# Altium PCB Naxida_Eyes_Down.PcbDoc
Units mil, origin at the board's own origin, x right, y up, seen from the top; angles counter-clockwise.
Board outline 2236.22 x 1401.57 mil, 2 copper layers (Top Layer, Bottom Layer); 34 components, 21 nets, 111 pads, 121 vias.
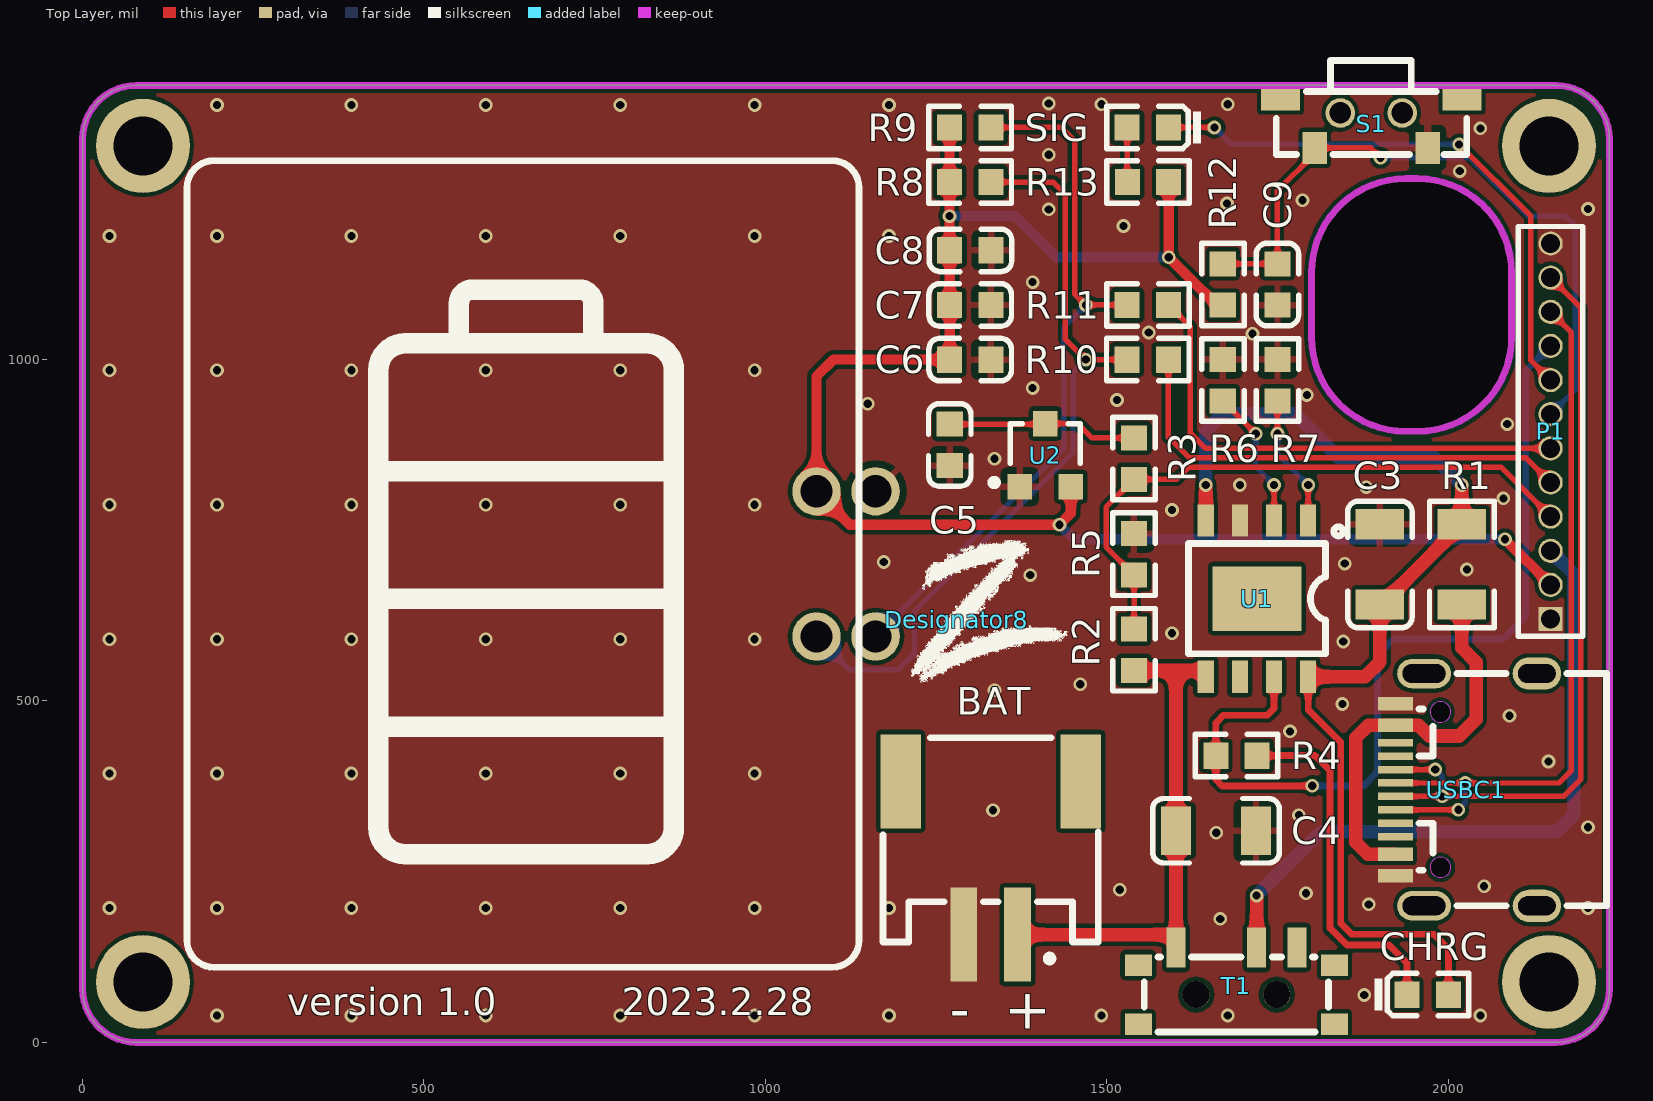
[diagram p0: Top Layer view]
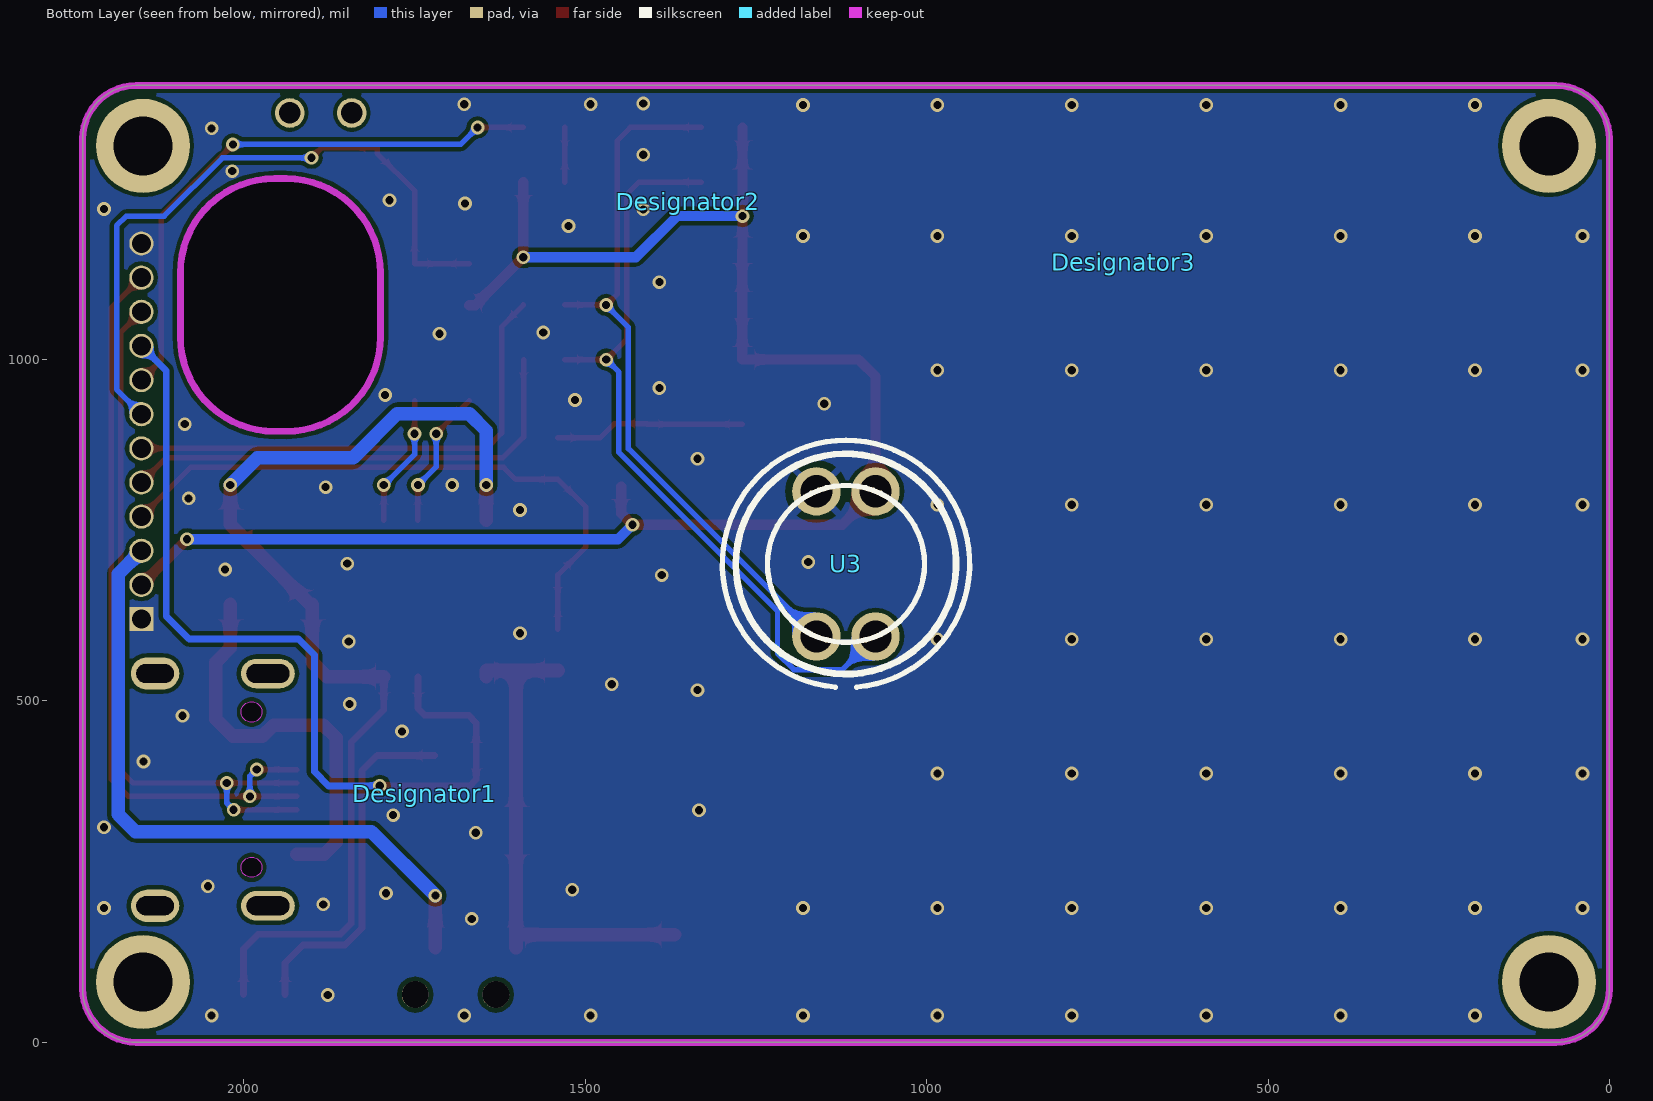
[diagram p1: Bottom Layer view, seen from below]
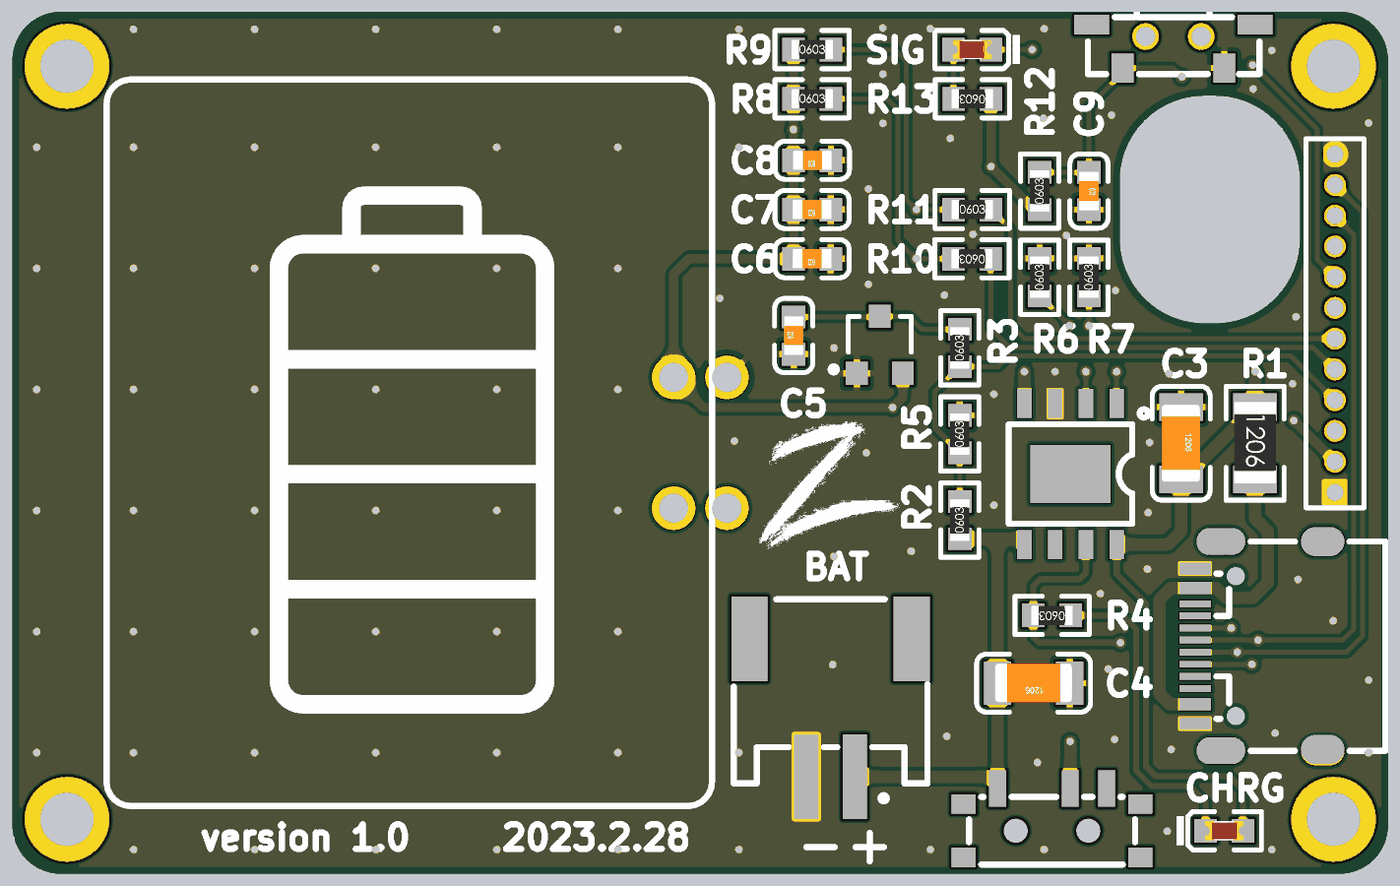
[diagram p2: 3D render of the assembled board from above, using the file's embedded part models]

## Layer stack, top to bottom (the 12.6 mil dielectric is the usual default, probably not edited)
Top Solder: solder mask 0.4, Solder Resist, Dk 3.5
Top Layer: signal copper 1.4
Dielectric 1: dielectric 12.6, FR-4, Dk 4.8
Bottom Layer: signal copper 1.4
Bottom Solder: solder mask 0.4, Solder Resist, Dk 3.5

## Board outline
78.74,0 cw(c78.74,78.74) 0,78.74 0,1322.83 cw(c78.74,1322.83) 78.74,1401.57 2157.48,1401.57 cw(c2157.48,1322.83) 2236.22,1322.83 2236.22,78.74 cw(c2157.48,78.74) 2157.48,0
cut-out: 1800,1032.58 ccw(c1937.58,1032.58) 1937.58,895 1955.2,895 ccw(c1955.2,1032.8) 2093,1032.8 2093,1127.2 ccw(c1955.2,1127.2) 1955.2,1265 1937.8,1265 ccw(c1937.8,1127.2) 1800,1127.2

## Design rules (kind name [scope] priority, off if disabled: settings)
Clearance [All] p1: gap=6 ignorepadtopadclearanceinfootprint=TRUE except(5: Arc-Via Track-Via SMDPad-Via THPad-Via Via-Via)
PolygonConnect PolygonConnect_2 [HasPad('P1-1','P1-12','U1-3','BAT-2','USBC1-A1','USBC1-A12')] p1: connectstyle=Direct reliefconductorwidth=10 reliefentries=4 polygonreliefangle="90 Angle" airgapwidth=10
PolygonConnect PolygonConnect_1 [IsVia] p2: connectstyle=Direct reliefconductorwidth=10 reliefentries=4 polygonreliefangle="90 Angle" airgapwidth=10
PolygonConnect [All] p3: connectstyle=Relief reliefconductorwidth=10 reliefentries=4 polygonreliefangle="90 Angle" airgapwidth=10
RoutingVias [All] p1: holewidth=12 width=20 viastyle="Through Hole" minholewidth=12 minwidth=20 maxholewidth=28 maxwidth=50
SolderMaskExpansion [All] p1: expansion=4 istentingtop=FALSE
Width [All] p1: maxlimit=30 minlimit=6 preferedwidth=8
30 further rules are at their usual default settings.

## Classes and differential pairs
component class Naxida_Eyes_Down: BAT C3 C4 C5 C6 C7 C8 C9 CHRG P1 R1 R2 R3 R4 R5 R6 R7 R8 R9 R10 R11 R12 R13 S1 SIG T1 U1 U2 U3 USBC1

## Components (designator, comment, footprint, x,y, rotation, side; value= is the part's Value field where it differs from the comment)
BAT "Header 2*1" COM_T_2.0_2P 1330,270 r180 top (schematic designator BAT1)
C3 "10uF" LC-1206_C 1900,700 r270 top
C4 "10uF" LC-1206_C 1660,310 r180 top
C5 "0.1uF" LC-0603_C 1270,875 r90 top
C6 "4.7uF" LC-0603_C 1300,1000 r180 top
C7 "0.1uF" LC-0603_C 1300,1080 r180 top
C8 "10nF" LC-0603_C 1300.32,1160 r180 top
C9 "Cap" LC-0603_C 1750,1110 r270 top value=0.1uF
CHRG "LED0" LC-0603_LED_S1 1970,70 r0 top
Designator1 "Comment" Z_NAHIDA_1 1735,365 r180 bottom locked
Designator2 "Comment" Z_NAHIDA_3 1349.49,1232.17 r180 bottom locked
Designator3 "Comment" Z_NAHIDA_4 711.43,1143.16 r180 bottom locked
Designator8 "Comment" Z_LOGO_MINI 1280,620 r0 top
P1 "Header 12*1" HDR12X1_A-1.27mm 2150,620 r90 top
R1 "0.4R" LC-1206_R 2020,700 r270 top
R2 "4.7K" LC-0603_R 1540,575 r90 top
R3 "1K" LC-0603_R 1540,855 r90 top
R4 "1.5K" LC-0603_R 1690,420 r180 top
R5 "4.7K" LC-0603_R 1540,715 r90 top
R6 "1.2K" LC-0603_R 1670,970 r90 top
R7 "4.7K" LC-0603_R 1750,970 r90 top
R8 "4.7K" LC-0603_R 1300,1260 r0 top
R9 "4.7K" LC-0603_R 1300,1340 r0 top
R10 "120R" LC-0603_R 1560,1000 r180 top
R11 "120R" LC-0603_R 1560.31,1080 r0 top
R12 "Res1" LC-0603_R 1670,1110 r90 top value=4.7K
R13 "Res1" LC-0603_R 1560.47,1260 r180 top value=4.7K
S1 "SW-PB" KEY_3*6*3.5 1884.11,1302.95 r180 top
SIG "LED0" LC-0603_LED_S1 1560.16,1340 r180 top
T1 "Header 3*1" KEY_3*7 1690,70 r180 top
U1 "TP4056" ESOP_4056 1720,650 r180 top
U2 "BAT54S" SOT-23 1410,860 r0 top
U3 "MLX90640" MLX90640 1118.11,700.79 r0 bottom locked
USBC1 "TYPE-C" TYPE-C-16P 2026.3,370.1 r90 top locked

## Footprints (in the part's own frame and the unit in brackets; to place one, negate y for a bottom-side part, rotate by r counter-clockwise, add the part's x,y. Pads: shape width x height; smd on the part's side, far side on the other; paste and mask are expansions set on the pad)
COM_T_2.0_2P [mm]
  rect 1x3.5 smd: 1(-1,2.85) 2(1,2.85)
  rect 1.5x3.5 smd: 3(3.35,-2.85) 4(-3.35,-2.85)
  silkscreen extent -4,-4.48 4,3.87
ESOP_4056 [mm]
  rect 0.6x1.2 smd mask+0.051: 1(-1.905,-2.908) 2(-0.635,-2.908) 3(0.635,-2.908) 4(1.905,-2.908) 5(1.905,2.908) 6(0.635,2.908) 7(-0.635,2.908) 8(-1.905,2.908)
  rect 3.3x2.4 smd mask+0.051: 9(0,0)
  silkscreen extent -3.2,-2.67 2.55,2.05
HDR12X1_A-1.27mm [mm] "Connector; Header; 12 Position"
  rect 0.9x0.9 hole 0.7: 1(0,0)
  round 0.9 hole 0.7: 2(1.27,0) 3(2.54,0) 4(3.81,0) 5(5.08,0) 6(6.35,0) 7(7.62,0) 8(8.89,0) 9(10.16,0) 10(11.43,0) 11(12.7,0) 12(13.97,0)
  silkscreen extent -0.64,-1.2 14.6,1.2
KEY_3*6*3.5 [mm]
  rect 0.9x1.2 smd: 1(-2.182,-0.179) 2(2.018,-0.179)
  rect 1.45x0.8 smd: ""(-3.457,-1.971) ""(3.293,-1.971)
  round 1.1 hole 0.8 unplated: ""(-1.232,-1.479) ""(1.068,-1.479)
  silkscreen extent -3.64,-3.43 3.45,0.07
KEY_3*7 [mm]
  rect 0.7x1.5 smd: 1(2.25,-1.75) 2(-0.75,-1.75) 3(-2.25,-1.75)
  rect 1x0.8 smd: 4(-3.65,1.1) 5(-3.65,-1.1) 6(3.65,-1.1) 7(3.65,1.1)
  round 1 hole 1 unplated: ""(-1.5,0) ""(1.5,0)
  silkscreen extent -3.43,-1.4 3.43,1.4
LC-0603_C [mm]
  rect 0.93x0.98 smd: 1(-0.77,0) 2(0.77,0)
  silkscreen extent -1.53,-0.79 1.54,0.79, body extent -0.8,-0.4 0.8,0.4, height 0.3
LC-0603_LED_S1 [mm]
  rect 0.93x0.98 smd: 1(0.77,0) 2(-0.77,0)
  silkscreen extent -1.98,-0.79 1.54,0.79, body extent -0.8,-0.4 0.8,0.4, height 0.6
LC-0603_R [mm]
  rect 0.93x0.98 smd: 1(-0.77,0) 2(0.77,0)
  silkscreen extent -1.53,-0.79 1.54,0.79, body extent -0.85,-0.4 0.85,0.4, height 0.56
LC-1206_C [mm]
  rect 1.13x1.8 smd: 1(-1.49,0) 2(1.49,0)
  silkscreen extent -2.36,-1.2 2.35,1.2, body extent -1.6,-0.81 1.6,0.79, height 1
LC-1206_R [mm]
  rect 1.13x1.8 smd: 1(-1.49,0) 2(1.49,0)
  silkscreen extent -2.36,-1.2 2.35,1.2, body extent -1.7,-0.86 1.65,0.87, height 0.85
MLX90640 [mm]
  round 1.8 hole 1.2 copper offset 0.001,0 mask+0.05: 1(-1.1,2.701) 2(-1.1,-2.699) 3(1.101,-2.699) 4(1.101,2.701)
  silkscreen extent -4.6,-4.6 4.6,4.58
SOT-23 [mm]
  rect 0.9x0.95 smd: 1(-0.95,-1.175) 2(0.95,-1.175) 3(0,1.175)
  silkscreen extent -2.03,-1.14 1.3,1.18, body extent -1.7,-0.8 1.7,0.8, height 1.5
TYPE-C-16P [mil]
  oval 47.2x70.9 hole 27.6 slot 55.1 at 90 deg mask+2: 0(-170.1,-103.7) 0(170.1,-103.7)
  oval 43.3x78.7 hole 27.6 slot 63 at 90 deg mask+2: 0(-170.1,61.6) 0(170.1,61.6)
  rect 19.7x51.2 smd mask+2: A1(-126,103.7) A4(-94.5,103.7) A9(94.5,103.7) A12(126,103.7)
  rect 11x51.2 smd mask+2: A5(-49.2,103.7) A6(-9.8,103.7) A7(9.8,103.7) A8(49.2,103.7) B5(68.9,103.7) B6(29.5,103.7) B7(-29.5,103.7) B8(-68.9,103.7)
  Keep-Out Layer board cut-out: 128.6,37.6 128.6,40.54 126.35,45.98 122.18,50.15 116.74,52.4 110.86,52.4 105.42,50.15 101.25,45.98 99,40.54 99,37.6 99,34.66 101.25,29.22 105.42,25.05 110.86,22.8 116.74,22.8 122.18,25.05 126.35,29.22 128.6,34.66 128.6,37.6 128.6,37.6
  Keep-Out Layer board cut-out: -99,37.6 -99,40.54 -101.25,45.98 -105.42,50.15 -110.86,52.4 -116.74,52.4 -122.18,50.15 -126.35,45.98 -128.6,40.54 -128.6,37.6 -128.6,34.66 -126.35,29.22 -122.18,25.05 -116.74,22.8 -110.86,22.8 -105.42,25.05 -101.25,29.22 -99,34.66 -99,37.6 -99,37.6
  silkscreen extent -170,-205 170,69
Z_LOGO_MINI [mil]
  silkscreen extent -66,-92 162,116
Z_NAHIDA_1 [mil]
Z_NAHIDA_3 [mil]
Z_NAHIDA_4 [mil]

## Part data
BAT P1 T1: "接插件"
C3 C4 C5 C6 C7 C8: library part Cap, "无极性电容"
C9: "无极性电容"
CHRG SIG: "发光二极管"
R1 R2 R3 R4 R5 R6 R7 R8 R9 R10 R11: library part Res1, "贴片电阻"
R12 R13: "贴片电阻"
S1: "微动开关"
U1: "锂电池充电管理"
U2: "肖特基二极管"
USBC1: Current Rating - Power (Max)=3A, JLCPCB Part Class="Extended Part", LCSC Part Name="Type-C 母座", Manufacturer=精拓金, Manufacturer Part=918-418K2023S40001

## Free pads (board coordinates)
  round 137.8 hole 86.61: 2(88.58,88.58) 2(88.58,1312.99) 2(2147.64,88.58) 2(2147.64,1312.99)

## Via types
v1: diameter 20, hole 12, Top Layer to Bottom Layer, tented both sides, 121 vias

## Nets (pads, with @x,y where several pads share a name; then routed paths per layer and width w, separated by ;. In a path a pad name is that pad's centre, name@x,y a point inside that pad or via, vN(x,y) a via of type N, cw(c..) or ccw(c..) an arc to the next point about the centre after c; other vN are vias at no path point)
3.3V: C6.2 C7.2 C8.2 P1.2 R8.1 R9.1 R12.1 R13.1 U2.2 U3.2 | length 2472.4
  Top Layer w15: R9.1 R8.1 v1(1269.69,1210.16) 1269.69,1160.31 C8.2 1270,1000.32 C6.2 1099.66,1000 1074.82,975.16 U3.2 1123.76,758.11 v1(1430.81,758.11) 1447.4,774.7 U2.2 ; R13.1 v1(1590.79,1149.92) 1661.02,1079.69 R12.1 ; v1(2083.15,736.85) P1.2
  Bottom Layer w15: v1(1269.69,1210.16) 1365.66,1210.16 1425.9,1149.92 v1(1590.79,1149.92) ; v1(1430.81,758.11) 1452.07,736.85 v1(2083.15,736.85)
BAT: BAT.1 C4.2 R2.1 T1.1 U1.5 | length 751.9
  Top Layer w20: BAT.1 T1.1@1601.34,157.8 ; R2.1 1601.34,544.69 ; T1.1@1601.34,138.9 T1.1@1601.34,157.8 ; U1.5 1645,544.69 1601.34,544.69 ; T1.1@1601.34,157.8 C4.2 1601.34,544.69
BAT_ADC: P1.4 R2.2 R3.1 R5.1 | length 900.2
  Top Layer w8: R2.2 R5.1 1499.12,725.57 1499.12,783.8 R3.1 1602.18,824.69 1619.49,842 2078,842 P1.4
BAT_OUT: P1.3 T1.2 | length 989.9
  Top Layer w20: T1.2 v1(1719.53,214.94)
  Bottom Layer w20: v1(1719.53,214.94) 1813.17,308.58 2158.6,308.58 2183.93,333.91 2183.93,686.07 P1.3
CHRG_GPIO: P1.9 R4.2 U1.7 | length 1295.2
  Top Layer w10: U1.7 1745,488.85 1735.34,479.19 1670.8,479.19 1659.68,468.08 R4.2 1659.68,385.09 1669.04,375.73 v1(1801.05,375.73)
  Bottom Layer w10: v1(1801.05,375.73) 1875.86,375.73 1896.58,396.45 1896.58,567.28 1919.89,590.59 2079.99,590.59 2113.77,624.37 2113.77,983.77 P1.9
GND: BAT.2 C3.1 C4.1 C5.1 C6.1 C7.1 C8.1 C9.2 P1.1 P1.12 R5.2 R6.2 R7.2 S1.1 U1.3 U2.1 U3.3 USBC1.A1 USBC1.A12
  other v1: 196.85,39.37 393.7,39.37 590.55,39.37 787.4,39.37 984.25,39.37 1181.1,39.37 1492.13,39.37 1677.16,39.37 2047.24,39.37 1877.11,69.45 1666.36,180.88 39.37,196.85 196.85,196.85 393.7,196.85 590.55,196.85 787.4,196.85 984.25,196.85 1181.1,196.85 2204.72,196.85 1883.77,202.07 1791.72,218.42 1518.91,223.55 2052.72,228.72 1660.27,307.16 2204.72,314.96 1781.42,332.88 1333.38,339.95 39.37,393.7 196.85,393.7 393.7,393.7 590.55,393.7 787.4,393.7 984.25,393.7 2147.01,411.35 1768.47,455.51 2089.96,478.41 1845.07,495.48 1335.53,515.89 1461.05,524.48 1846.22,587.22 39.37,590.55 196.85,590.55 393.7,590.55 590.55,590.55 787.4,590.55 984.25,590.55 1595.51,599.34 1388.09,684.33 2027.44,692.53 1848.63,701.17 1173.53,703.64 1595.51,779.8 39.37,787.4 196.85,787.4 393.7,787.4 590.55,787.4 787.4,787.4 984.25,787.4 2080.95,796.72 1880.26,813.24 1695,816.33 1335.53,854.9 2086.61,905.51 1149.93,935.37 1514.97,940.88 1793.13,948.23 1391.44,958.45 39.37,984.25 196.85,984.25 393.7,984.25 590.55,984.25 787.4,984.25 984.25,984.25 1713.37,1037.78 1561.59,1039.7 1391.44,1113.47 39.37,1181.1 196.85,1181.1 393.7,1181.1 590.55,1181.1 787.4,1181.1 984.25,1181.1 1181.1,1181.1 1524.48,1195.62 1415,1220 2204.72,1220.47 1676.01,1228.66 1786.76,1233.5 2017,1276 1415,1300 2047.24,1338.58 196.85,1372.95 393.7,1372.95 590.55,1372.95 787.4,1372.95 984.25,1372.95 1181.1,1372.95 1492.13,1373.95 1677.16,1373.95 1415,1375
IIC_SCL: P1.6 R11.2 | length 737.6
  Top Layer w8: R11.2 1622.54,1048.09 1622.54,892.36 1644.9,870 P1.6
IIC_SDA: P1.5 R10.1 | length 700.7
  Top Layer w8: R10.1 1590.31,886.59 1620.9,856 2114,856 P1.5
KEY_GPIO: C9.1 P1.7 R12.2 S1.2 | length 992.2
  Top Layer w8: R12.2 C9.1 1750,1247.34 1804.64,1301.99 S1.2 1886.46,1310 v1(1900.97,1295.49)
  Bottom Layer w8: v1(1900.97,1295.49) 2031.42,1295.49 2116.71,1210.2 2172.1,1210.2 2186.25,1196.04 2186.25,956.25 P1.7
LED_GPIO: P1.8 SIG.2 | length 836.3
  Top Layer w8: SIG.2 v1(1657.67,1340) ; v1(2016.02,1315.04) 2121,1210.06 2121,999 P1.8
  Bottom Layer w8: v1(1657.67,1340) 1682.44,1315.23 v1@2016.02,1315.23
NetC3_2: C3.2 CHRG.1 R1.1 U1.4 U1.8 | length 1605.5
  Top Layer w10: U1.8 1795,487.23 1842.77,439.46 1842.77,173.98 1858.27,158.48 1978.7,158.48 2000.32,136.86 CHRG.1
  Top Layer w20: U1.4 v1(1645,816.33) ; U1.8 1878.25,535.5 1900,557.25 C3.2 1902.68,641.34 R1.1 v1(2020,816.33)
  Bottom Layer w20: v1(1645,816.33) 1645,895.89 1670.04,920.93 1775.23,920.93 1840.1,856.05 1980.28,856.05 v1(2020,816.33)
NetC5_2: C5.2 R3.2 U2.3 | length 279.1
  Top Layer w8: C5.2 1409.05,905.32 U2.3 1457.47,906.26 1478.41,885.32 R3.2
NetCHRG_2: CHRG.2 R4.1 | length 526.4
  Top Layer w10: R4.1 1804.71,420 1826.77,397.94 1826.77,167.35 1851.64,142.48 1913.27,142.48 1939.69,116.06 CHRG.2
NetR6_1: R6.1 U1.2 | length 206.3
  Top Layer w8: R6.1 v1(1718.35,891.33) ; U1.2 v1(1745,816.33)
  Bottom Layer w8: v1(1718.35,891.33) 1718.35,842.98 v1(1745,816.33)
NetR7_1: R7.1 U1.1 | length 193.8
  Top Layer w8: v1(1750,891.33) R7.1 ; U1.1 v1(1795,816.33)
  Bottom Layer w8: v1(1750,891.33) 1750,861.33 v1(1795,816.33)
NetR8_2: R8.2 R10.2 U3.1 | length 1139
  Top Layer w8: R8.2 1421.46,1260 1439.05,1242.41 1439.05,1030.09 v1(1469.14,1000) R10.2
  Bottom Layer w8: U3.1 1123.31,545.97 1194.54,545.97 1218.46,569.89 1218.46,631.68 1450.71,863.93 1450.71,981.57 v1(1469.14,1000)
NetR9_2: R9.2 R11.1 U3.4 | length 1051.9
  Top Layer w8: R9.2 1433.82,1340 1453.05,1320.78 1453.05,1096.41 v1(1469.45,1080) R11.1
  Bottom Layer w8: U3.4 1436.71,869.73 1436.71,1047.25 v1(1469.45,1080)
NetR13_2: R13.2 SIG.1 | length 80.1
  Top Layer w8: SIG.1 1529.84,1260.32 R13.2
USB_D+: P1.11 USBC1.A6 USBC1.B6 | length 1137.2
  Top Layer w8: USBC1.A6 v1(1991.19,360.3) 2169.11,360.3 2194.52,385.71 2194.52,1075.48 P1.11 ; USBC1.B6 v1(1981.19,399.6)
  Bottom Layer w8: v1(1981.19,399.6) 1991.19,389.6 v1(1991.19,360.3)
USB_D-: P1.10 USBC1.A7 USBC1.B7 | length 1085.8
  Top Layer w8: USBC1.B7 v1(2014.98,340.6) ; USBC1.A7 v1(2024.98,379.9) 2162.29,379.9 2180.52,398.13 2180.52,1039.48 P1.10
  Bottom Layer w8: v1(2014.98,340.6) 2024.98,350.6 v1(2024.98,379.9)
VCC_IN: R1.2 USBC1.A4 USBC1.A9 | length 595.5
  Top Layer w20: USBC1.A4 1882.18,275.6 1864.81,292.97 1864.81,446.14 1883.27,464.6 USBC1.A9 1956.63,464.6 1972.56,448.67 2016.29,448.67 2040.99,473.38 2040.99,556.88 2020,577.87 R1.2
pads on no net: BAT.3 BAT.4 S1. T1. T1.3 T1.4 T1.5 T1.6 T1.7 U1.6 U1.9 USBC1.0 USBC1.A5 USBC1.A8 USBC1.B5 USBC1.B8

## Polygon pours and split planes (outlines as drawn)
GND on Top Layer "Top Layer-No Net" (solid, remove dead copper, pour order 4): 0,0 2236.22,0 2236.22,1401.57 0,1401.57
GND on Bottom Layer "Top Layer-No Net" (solid, remove dead copper, pour order 6): 0,0 2236.22,0 2236.22,1401.57 0,1401.57

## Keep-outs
Keep-Out Layer:
  lines w10: 1954.99,895 1937.58,895 cw(c1937.58,1032.58) 1800,1032.58 1800,1127.2 cw(c1937.8,1127.2) 1937.8,1265 1955.2,1265 cw(c1955.2,1127.2) 2093,1127.2 2093,1032.8 cw(c1955.2,1032.8) 1955.2,895 ; 0,78.74 ccw(c78.74,78.74) 78.74,0 2157.48,0 ccw(c2157.48,78.74) 2236.22,78.74 2236.22,1322.83 ccw(c2157.48,1322.83) 2157.48,1401.57 78.74,1401.57 ccw(c78.74,1322.83) 0,1322.83 0,78.74

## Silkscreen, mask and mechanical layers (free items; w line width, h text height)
Top Overlay:
  lines w10: 152.95,149.53 ccw(c192.32,149.53) 192.32,110.16 1097.83,110.16 ccw(c1097.83,149.53) 1137.2,149.53 1137.2,1251.89 ccw(c1097.83,1251.89) 1097.83,1291.26 192.32,1291.26 ccw(c192.32,1251.89) 152.95,1251.89 152.95,149.53
  lines w30: 433.07,462.6 866.14,462.6 ; 433.07,649.61 866.14,649.61 ; 433.07,836.61 866.14,836.61 ; 551.18,1023.62 472.44,1023.62 ccw(c472.44,984.25) 433.07,984.25 433.07,314.96 ccw(c472.44,314.96) 472.44,275.59 826.77,275.59 ccw(c826.77,314.96) 866.14,314.96 866.14,984.25 ccw(c826.77,984.25) 826.77,1023.62 748.03,1023.62 ; 551.18,1023.62 551.18,1082.68 cw(c570.87,1082.68) 570.87,1102.36 728.35,1102.36 cw(c728.35,1082.68) 748.03,1082.68 748.03,1023.62 ; 551.18,1023.62 748.03,1023.62
  text "version 1.0" at 300,40 h40
  text "2023.2.28" at 790,40 h40
  text "-" at 1270,20 h60
  text "+" at 1350,20 h60
Mechanical 1:
  drawing of 34589 lines, arcs and shapes, not listed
